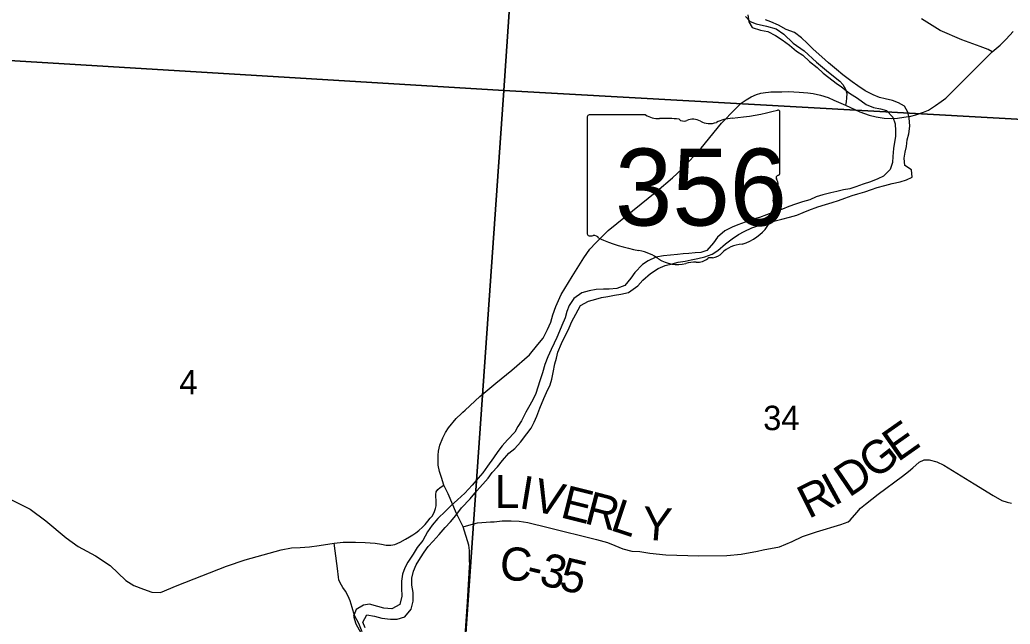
# Model space of a CAD drawing. Extents: x 0 to 34, y 0 to 22.
# Drawn here: x 3.709 to 5.404, y 18.871 to 19.906 of the extents above; entities that cross this region are included whole.
import ezdxf

# ---------------------------------------------------------------- set-up
doc = ezdxf.new("R2010")
doc.units = 0
for name, color, linetype in [('GM_X_Corporation', 7, 'Continuous'), ('GM_X_County_Road', 7, 'Continuous'), ('GM_X_County_Road_Text', 7, 'Continuous'), ('GM_X_Major_River', 7, 'Continuous'), ('GM_X_Section_Text', 7, 'Continuous'), ('GM_X_State_Location', 7, 'Continuous'), ('GM_X_State_Route', 7, 'Continuous'), ('GM_X_State_Shield', 7, 'Continuous'), ('GM_X_Township_Road', 7, 'Continuous')]:
    doc.layers.add(name, color=color, linetype=linetype)

msp = doc.modelspace()

# ---------------------------------------------------------------- linework, layer by layer
at = {"layer": 'GM_X_Corporation'}
for points in [[(4.607, 20.8038), (4.5379, 19.7849), (3.5308, 19.8461), (3.6063, 20.8752)], [(5.6414, 20.7385), (5.5693, 19.7272), (4.5379, 19.7849), (4.607, 20.8038)], [(3.5308, 19.8461), (4.5379, 19.7849), (4.465, 18.749), (3.459, 18.812), (3.474, 19.0276), (3.5026, 19.4408)], [(4.5379, 19.7849), (5.5693, 19.7272), (5.5363, 19.3151), (5.5032, 18.9017), (5.4857, 18.6848), (4.465, 18.749)]]:
    msp.add_lwpolyline(points, close=True, dxfattribs=at)
at = {"layer": 'GM_X_County_Road'}
msp.add_lwpolyline([(4.4679, 19.0373), (4.4779, 19.0404), (4.4929, 19.0441), (4.5151, 19.046), (4.5212, 19.0462), (4.5351, 19.0475), (4.5503, 19.0479), (4.5639, 19.0472), (4.5787, 19.0447), (4.6137, 19.0365), (4.6961, 19.0158), (4.7154, 19.0105), (4.7277, 19.0053), (4.7413, 18.9998), (4.7567, 18.9961), (4.7707, 18.9951), (4.7878, 18.9926), (4.8147, 18.9897), (4.8716, 18.9879), (4.9192, 18.9885), (4.9437, 18.9905), (4.9718, 18.9959), (4.9816, 18.9979), (5.0094, 19.0035), (5.0206, 19.0078), (5.0312, 19.0126), (5.0486, 19.0207), (5.073, 19.0287), (5.1145, 19.0415), (5.1272, 19.0459), (5.1305, 19.0487), (5.1419, 19.0618), (5.1482, 19.0693), (5.1568, 19.0762), (5.1785, 19.0932), (5.2199, 19.1245), (5.2302, 19.1323), (5.2377, 19.1387), (5.2487, 19.148), (5.2573, 19.1525), (5.2658, 19.1522), (5.2786, 19.1488), (5.2905, 19.1432), (5.3429, 19.1112), (5.3753, 19.091), (5.3899, 19.0824), (5.399, 19.08), (5.4063, 19.0782)], dxfattribs=at)
at = {"layer": 'GM_X_Major_River'}
for points in [[(4.9554, 19.9146), (4.9569, 19.9028), (4.9626, 19.8929), (4.977, 19.8884), (4.9895, 19.8861), (5.0024, 19.8789), (5.0142, 19.8716), (5.0267, 19.8625), (5.0388, 19.8522), (5.0495, 19.8454), (5.0608, 19.8348), (5.0737, 19.8241), (5.084, 19.8146), (5.0938, 19.807), (5.1064, 19.7975), (5.1158, 19.7914), (5.1295, 19.7804), (5.1431, 19.7716), (5.1576, 19.761), (5.1705, 19.7557), (5.1826, 19.7538), (5.1925, 19.7507), (5.2035, 19.7393), (5.2072, 19.7279), (5.208, 19.7161), (5.208, 19.7059), (5.2065, 19.6964), (5.2046, 19.6854), (5.2034, 19.6721), (5.2027, 19.6618), (5.1989, 19.6497), (5.1875, 19.6383), (5.178, 19.6338), (5.1651, 19.6285), (5.1529, 19.6243), (5.14, 19.6201), (5.1298, 19.6167), (5.1192, 19.6145), (5.1078, 19.6122), (5.0975, 19.6095), (5.0839, 19.6061), (5.0721, 19.6027), (5.0615, 19.5978), (5.0486, 19.594), (5.0368, 19.5902), (5.0254, 19.5861), (5.0144, 19.5819), (5.0027, 19.5774), (4.9875, 19.572), (4.975, 19.5675), (4.9624, 19.5637), (4.9507, 19.5592), (4.9381, 19.5546), (4.9287, 19.5508), (4.9158, 19.5444), (4.9036, 19.5338), (4.8968, 19.5239), (4.885, 19.5106), (4.8751, 19.5076), (4.8649, 19.5069), (4.8543, 19.5057), (4.8448, 19.505), (4.8349, 19.5042), (4.8228, 19.5031), (4.811, 19.5016), (4.7977, 19.4993), (4.7845, 19.4929), (4.775, 19.4868)], [(5.1435, 19.7929), (5.1337, 19.7997), (5.1181, 19.8115), (5.1071, 19.821), (5.0935, 19.8324), (5.0817, 19.8427), (5.0673, 19.856), (5.0567, 19.8659), (5.0472, 19.8754), (5.0351, 19.8845), (5.021, 19.8895), (5.0077, 19.8971), (4.9949, 19.9028), (4.9854, 19.9062)], [(4.4082, 19.0038), (4.4169, 19.0132), (4.4268, 19.0242), (4.4374, 19.0364), (4.4462, 19.0463), (4.4553, 19.0569), (4.4651, 19.0702), (4.48, 19.0857), (4.491, 19.0986), (4.502, 19.1108), (4.5111, 19.1206), (4.5175, 19.1305), (4.527, 19.1404), (4.5354, 19.151), (4.5464, 19.1639), (4.5563, 19.1715), (4.5661, 19.1828), (4.5771, 19.1969), (4.5847, 19.2068), (4.5897, 19.2166), (4.5942, 19.2269), (4.5992, 19.2409), (4.6064, 19.2576), (4.6109, 19.2679), (4.617, 19.2808), (4.6197, 19.2906), (4.6223, 19.3016), (4.625, 19.3165), (4.6277, 19.3267), (4.6303, 19.3366), (4.6364, 19.3518), (4.6497, 19.3783), (4.6539, 19.389), (4.6607, 19.4019), (4.6687, 19.4167), (4.6824, 19.4242), (4.6949, 19.4276), (4.7051, 19.4303), (4.7157, 19.4322), (4.7271, 19.4341), (4.7381, 19.4363), (4.751, 19.439), (4.767, 19.4504), (4.7757, 19.4599), (4.789, 19.4716), (4.8019, 19.48), (4.814, 19.4853), (4.8258, 19.4883), (4.8361, 19.4906), (4.8478, 19.4928), (4.8581, 19.4951), (4.8698, 19.497), (4.8816, 19.5), (4.8945, 19.5045), (4.904, 19.511), (4.9169, 19.522), (4.9287, 19.5311), (4.9393, 19.5383), (4.9491, 19.5436), (4.9624, 19.5497), (4.9761, 19.5542), (4.9882, 19.5576), (5.0023, 19.5614), (5.0137, 19.5644), (5.0266, 19.5682), (5.0391, 19.5712), (5.0501, 19.5762), (5.0596, 19.58), (5.0751, 19.5856), (5.0884, 19.5894), (5.0994, 19.5932), (5.1104, 19.5966), (5.1214, 19.6004), (5.134, 19.6049), (5.1438, 19.608), (5.1556, 19.6114), (5.167, 19.6152), (5.1768, 19.6186), (5.1897, 19.6224), (5.2023, 19.6258), (5.2159, 19.6284), (5.2266, 19.6318), (5.2364, 19.6367), (5.2353, 19.6489), (5.2239, 19.6565), (5.2228, 19.669), (5.2243, 19.6793), (5.2266, 19.6892), (5.2281, 19.7005), (5.2308, 19.7108), (5.2323, 19.7241), (5.2315, 19.7381), (5.2293, 19.7476), (5.2232, 19.7583), (5.213, 19.764), (5.2027, 19.7678), (5.1906, 19.7708), (5.1807, 19.7731), (5.1697, 19.7773), (5.1561, 19.7842), (5.1435, 19.7929)], [(4.775, 19.4868), (4.7621, 19.4732), (4.7552, 19.4633), (4.745, 19.4508), (4.7309, 19.4458), (4.718, 19.4447), (4.7085, 19.4447), (4.6956, 19.444), (4.6835, 19.4417), (4.6714, 19.4383), (4.6577, 19.4284), (4.6497, 19.4167), (4.6455, 19.4061), (4.6425, 19.3954), (4.6372, 19.3825), (4.633, 19.3726), (4.6284, 19.3616), (4.6239, 19.3522), (4.6189, 19.3415), (4.6129, 19.3286), (4.6079, 19.3157), (4.6038, 19.3013), (4.5996, 19.2876), (4.5958, 19.2766), (4.5924, 19.266), (4.5882, 19.2561), (4.5825, 19.2459), (4.5753, 19.2337), (4.5677, 19.2193), (4.5616, 19.2094), (4.5563, 19.1999), (4.5441, 19.1863), (4.5346, 19.176), (4.5274, 19.1666), (4.5202, 19.1555), (4.5096, 19.1415), (4.5016, 19.1301), (4.494, 19.1206), (4.4838, 19.1089), (4.4709, 19.0952), (4.4587, 19.0838), (4.4477, 19.074), (4.4378, 19.0645), (4.4245, 19.0516), (4.4151, 19.0406), (4.4071, 19.0288), (4.3991, 19.014), (4.3896, 19.0019), (4.3824, 18.9905), (4.3737, 18.9768), (4.3683, 18.967), (4.3645, 18.9567), (4.3626, 18.9442), (4.3626, 18.9324), (4.363, 18.9187), (4.36, 18.9047), (4.3463, 18.8971), (4.3323, 18.8983), (4.322, 18.9009), (4.308, 18.9051), (4.2977, 18.9036), (4.2848, 18.896), (4.2807, 18.8846), (4.2844, 18.8713), (4.2928, 18.8561)], [(4.3004, 18.8645), (4.2962, 18.8744), (4.303, 18.8865), (4.3163, 18.8846), (4.3288, 18.8812), (4.344, 18.8793), (4.355, 18.8793), (4.3683, 18.8834), (4.3789, 18.8967), (4.3824, 18.91), (4.3824, 18.9248), (4.3805, 18.9373), (4.3801, 18.9495), (4.3831, 18.9613), (4.3877, 18.9726), (4.3949, 18.9844), (4.4014, 18.9943), (4.4082, 19.0038)]]:
    msp.add_lwpolyline(points, dxfattribs=at)
at = {"layer": 'GM_X_State_Route'}
for points in [[(5.296, 19.7734), (5.3038, 19.7814), (5.3736, 19.851), (5.387, 19.8625), (5.3975, 19.8729), (5.4096, 19.8858)], [(4.4716, 19.2376), (4.4966, 19.2609), (4.5239, 19.2836), (4.5517, 19.3056), (4.5814, 19.332), (4.5957, 19.3501), (4.6049, 19.3608), (4.6127, 19.3753), (4.6182, 19.388), (4.6218, 19.4007), (4.6266, 19.4147), (4.636, 19.4356), (4.6548, 19.4661), (4.6749, 19.4983), (4.6851, 19.5131), (4.6952, 19.5241), (4.7164, 19.5451), (4.7996, 19.6124), (4.8263, 19.6353), (4.8428, 19.6507), (4.8757, 19.6864), (4.9104, 19.7287), (4.9334, 19.753), (4.944, 19.763), (4.9523, 19.7691), (4.961, 19.7742), (4.9701, 19.778), (4.9773, 19.7801), (4.9855, 19.7814), (4.9906, 19.782)], [(4.9906, 19.782), (4.9946, 19.7824), (5.0046, 19.7829), (5.0133, 19.7829), (5.0249, 19.7831), (5.0433, 19.7822), (5.0579, 19.7812), (5.067, 19.7799), (5.0795, 19.7767), (5.0927, 19.7727), (5.1022, 19.7685), (5.1225, 19.7598), (5.1469, 19.7486), (5.1632, 19.7426), (5.175, 19.7401), (5.1884, 19.7376), (5.2006, 19.7369), (5.2112, 19.7373), (5.222, 19.739), (5.2343, 19.7412), (5.2426, 19.7435), (5.2559, 19.7477), (5.2642, 19.7515), (5.2697, 19.7545), (5.2767, 19.7594), (5.2862, 19.7659), (5.2944, 19.7719), (5.296, 19.7734)], [(4.4792, 18.9786), (4.4787, 18.997), (4.4776, 19.006), (4.4679, 19.0373), (4.4625, 19.0488), (4.4568, 19.0604), (4.4422, 19.0941), (4.4352, 19.1087), (4.4308, 19.1218), (4.4278, 19.1324), (4.4255, 19.1434), (4.4251, 19.1515), (4.4251, 19.1604), (4.4259, 19.1672), (4.4282, 19.1773), (4.4331, 19.19), (4.438, 19.1991), (4.4428, 19.2072), (4.456, 19.2228), (4.4654, 19.2314), (4.4673, 19.2337), (4.4716, 19.2376)], [(4.4701, 18.8269), (4.4757, 18.9089), (4.4791, 18.9687), (4.4793, 18.9745), (4.4792, 18.9786)]]:
    msp.add_lwpolyline(points, dxfattribs=at)
at = {"layer": 'GM_X_State_Shield'}
for p, q in [((5.0102, 19.6433), (5.0102, 19.748)), ((4.6806, 19.7396), (4.6806, 19.5395)), ((4.7804, 19.7431), (4.6838, 19.7431)), ((5.0102, 19.6434), (5.0102, 19.6433))]:
    msp.add_line(p, q, dxfattribs=at)
for centre, major_axis, start_param, end_param in [((4.8928, 20.0159), (0.3495, 0), 4.814394, 5.042369), ((5.0065, 19.7485), (0.00367, 0), 6.141152, 7.989035), ((4.6844, 19.74), (0.00382, 0), 1.712693, 3.28349), ((4.8034, 19.7663), (0.037, 0), 4.042523, 4.731795), ((4.8156, 19.6307), (0.133, 0), 1.404758, 1.657858), ((4.8458, 19.7411), (0.0107, 0), 3.836095, 5.185415), ((4.8615, 19.718), (0.0222, 0), 0.950623, 2.079405), ((4.8902, 19.7497), (0.0267, 0), 4.081561, 5.145723), ((4.9374, 19.6819), (0.0703, 0), 1.699011, 2.107814), ((5.0093, 19.6357), (0.00568, 0), 1.883978, 3.671073), ((4.9732, 19.6224), (0.0341, 0), 5.934695, 6.695948), ((5.0063, 19.6429), (0.00393, 0), 5.05454, 6.418171), ((5.0233, 19.5995), (0.0248, 0), 2.387724, 3.262537), ((4.9124, 19.5862), (0.0874, 0), 5.101752, 6.440018), ((4.6844, 19.5391), (0.00385, 0), 3.00124, 4.508301), ((4.685, 19.5595), (0.0294, 0), 4.665946, 4.897461), ((4.691, 19.528), (0.0106, 0), 0.519207, 1.627899), ((4.8248, 19.7078), (0.2524, 0), 4.195997, 4.488961), ((4.7496, 19.4496), (0.079, 0), 0.823519, 1.323587), ((4.9492, 19.4833), (0.0479, 0), 1.647645, 2.488434), ((4.835, 19.527), (0.0501, 0), 4.026481, 4.996735), ((4.8676, 19.512), (0.0267, 0), 4.691044, 5.507374), ((4.8918, 19.4926), (0.00752, 0), 1.147584, 2.315152), ((4.8886, 19.5201), (0.0282, 0), 4.937069, 5.64225), ((4.864, 19.4578), (0.0412, 0), 1.495662, 1.94098)]:
    msp.add_ellipse(centre, major_axis=major_axis, ratio=0.8, start_param=start_param, end_param=end_param, dxfattribs=at)
at = {"layer": 'GM_X_Township_Road'}
for points in [[(4.9514, 19.9118), (4.9592, 19.903), (4.9697, 19.8991), (4.9872, 19.895), (5.0038, 19.8908), (5.0168, 19.8816), (5.0329, 19.8662), (5.0516, 19.8526), (5.0726, 19.8336), (5.0936, 19.8163), (5.113, 19.8011), (5.1181, 19.7954), (5.1223, 19.7875), (5.1248, 19.7797), (5.1243, 19.7726), (5.1238, 19.7657), (5.1225, 19.7598)], [(5.3736, 19.851), (5.3668, 19.8551), (5.3531, 19.8601), (5.3217, 19.872), (5.2844, 19.8879), (5.2525, 19.9079)], [(3.6882, 19.0872), (3.7271, 19.0679), (3.7537, 19.0479), (3.7886, 19.0188), (3.8094, 19.0039), (3.8389, 18.9881), (3.8639, 18.9713), (3.8911, 18.9454), (3.9047, 18.9372), (3.9209, 18.9305), (3.9351, 18.9258), (3.9503, 18.9251), (3.9788, 18.9368), (4.0633, 18.9704), (4.0953, 18.9812), (4.1567, 18.9982), (4.1744, 19.0014), (4.1893, 19.002), (4.2054, 19.0033), (4.2219, 19.0055), (4.2472, 19.0094), (4.2625, 19.0113), (4.2758, 19.0115), (4.2836, 19.0111), (4.3006, 19.0105), (4.3177, 19.0094), (4.3285, 19.0077), (4.3366, 19.0062), (4.3442, 19.0062), (4.3514, 19.0075), (4.3601, 19.0113), (4.3692, 19.0164), (4.3764, 19.0204), (4.3819, 19.024), (4.3874, 19.0274), (4.3922, 19.0314), (4.3986, 19.0369), (4.4033, 19.0414), (4.4079, 19.0471), (4.4115, 19.0526), (4.4149, 19.0558), (4.4185, 19.0619), (4.4208, 19.0687), (4.4217, 19.0736), (4.4219, 19.0778), (4.4221, 19.0835), (4.4213, 19.0886), (4.4215, 19.0928), (4.4221, 19.0973), (4.4246, 19.1013), (4.4287, 19.1047), (4.4352, 19.1087)], [(4.2955, 18.8576), (4.2896, 18.8722), (4.2821, 18.8858), (4.2781, 18.8991), (4.2749, 18.9107), (4.2711, 18.9188), (4.2667, 18.9275), (4.262, 18.9338), (4.2574, 18.9417), (4.2555, 18.9465), (4.2546, 18.951), (4.2529, 18.9664), (4.2519, 18.9745), (4.2472, 19.0094)]]:
    msp.add_lwpolyline(points, dxfattribs=at)

# ---------------------------------------------------------------- texts
at = {"layer": 'GM_X_County_Road_Text'}
for s, rotation, p in [('E', 35.1296, (5.212, 19.1476)), ('G', 37.9142, (5.1731, 19.1173)), ('D', 34.2098, (5.1285, 19.0868)), ('L', 0.0386, (4.522, 19.0695)), ('I', 350.7173, (4.5621, 19.0697)), ('V', 346.2288, (4.584, 19.0662)), ('R', 26.4987, (5.0591, 19.0506)), ('I', 28.7429, (5.103, 19.0725)), ('E', 345.9534, (4.6325, 19.0543)), ('R', 345.3977, (4.6736, 19.0441)), ('L', 341.6274, (4.7178, 19.0326)), ('Y', 355.3769, (4.7724, 19.0163)), ('C', 355.8749, (4.5294, 18.9474)), ('3', 346.4863, (4.5962, 18.939)), ('5', 346.4686, (4.6302, 18.9308)), ('-', 346.5695, (4.5735, 18.9444))]:
    msp.add_text(s, height=0.0568, rotation=rotation, dxfattribs=at).set_placement(p)
at = {"layer": 'GM_X_Section_Text'}
for s, height, p in [('4', 0.0419, (3.9823, 19.2642)), ('34', 0.04186, (4.9815, 19.2031))]:
    msp.add_text(s, height=height, rotation=0, dxfattribs=at).set_placement(p)
at = {"layer": 'GM_X_State_Location'}
msp.add_text('356', height=0.000189, rotation=0, dxfattribs=at).set_placement((4.7748, 19.6125))
for s in ['s', 'r']:
    msp.add_text(s, height=0.000189, dxfattribs=at).set_placement((4.8417, 19.6263))
at = {"layer": 'GM_X_State_Shield'}
msp.add_text('356', height=0.13184, dxfattribs=at).set_placement((4.728, 19.5536))

doc.saveas('drawing.dxf')
